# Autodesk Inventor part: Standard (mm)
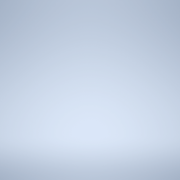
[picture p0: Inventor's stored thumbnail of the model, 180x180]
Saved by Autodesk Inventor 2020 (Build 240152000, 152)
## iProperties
Created: 2019-02
Part Number: Standard (mm)
Material: Ogólny
Document SubType Name: Modeling
Density: 1 g/cm^3
Appearance: Domyślna
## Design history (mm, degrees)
